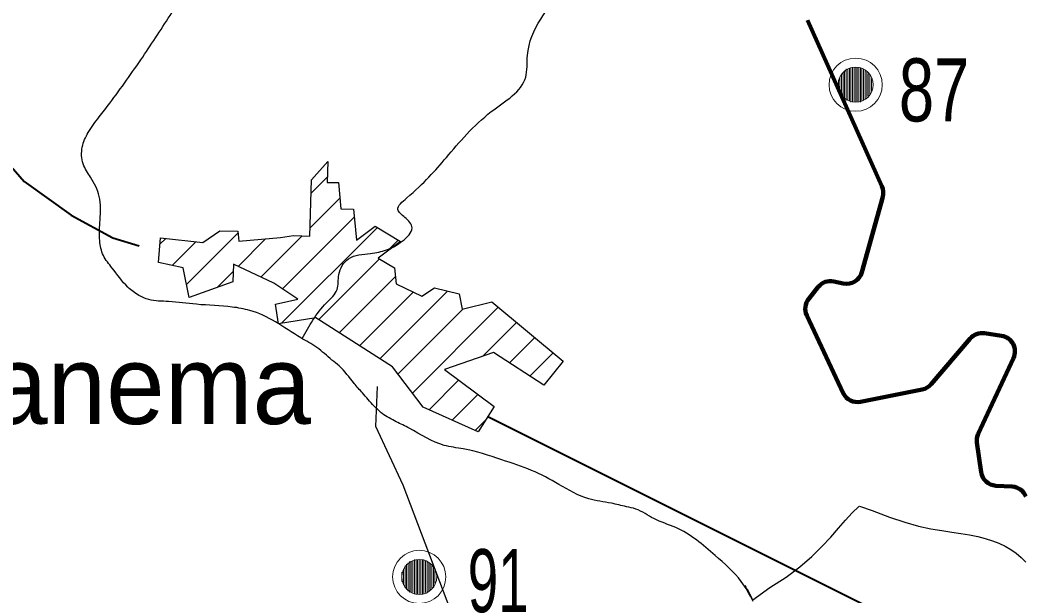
# Model space of a CAD drawing. Extents: x 553962 to 842807, y 8883888 to 9032388.
# Drawn here: x 690520 to 696901, y 8961682 to 8965336 of the extents above; entities that cross this region are included whole.
import ezdxf

# ---------------------------------------------------------------- set-up
doc = ezdxf.new("R2010")
doc.units = 0
doc.header["$LTSCALE"] = 160
for name, color, linetype, lineweight in [('15', 7, 'Continuous', 25), ('21', 7, 'Continuous', 25), ('27', 7, 'Continuous', 90), ('28', 7, 'Continuous', 13), ('32', 7, 'Continuous', 13), ('33', 7, 'Continuous', 13), ('7', 7, 'Continuous', 90)]:
    doc.layers.add(name, color=color, linetype=linetype, lineweight=lineweight)
doc.layers.add('29', color=7, linetype='Continuous')

msp = doc.modelspace()

# ---------------------------------------------------------------- linework, layer by layer
at = {"layer": '15', "lineweight": 40}
for points in [[(678613, 8973314.2), (678848.5, 8973159.5), (686496, 8968269.5), (688991.1, 8966516.2), (690142.8, 8964774.6), (690545.4, 8964311.7), (690844.1, 8964097.1), (691108, 8963953.4), (691274.5, 8963904.3)], [(693487.4, 8962819.8), (696836.9, 8961144.8), (697384.1, 8960961.8), (697603.7, 8960973.6), (697714.4, 8961082.3), (698321.2, 8961447.4), (698679, 8961567.8), (700187.3, 8961472.5), (701093.5, 8961547), (704410.2, 8961560.7)]]:
    msp.add_lwpolyline(points, dxfattribs=at)
at = {"layer": '15'}
msp.add_lwpolyline([(691240.8, 8956578.2), (692809.2, 8960246.9), (693257.6, 8961326.5), (693299.9, 8961463.3), (692951.1, 8962385.1), (692776, 8962756.9), (692786.9, 8963010.2)], dxfattribs=at)
at = {"layer": '21'}
for points in [[(695169, 8961656.4), (695276, 8961734.9), (695379, 8961800.8), (695467.1, 8961866.7), (695542.4, 8961931.7), (695606.8, 8961994.7), (695662.7, 8962054.9), (695711.8, 8962111.2), (695756.5, 8962162.8), (695798.7, 8962208.5), (695840.2, 8962247.9), (695844.8, 8962251.7), (695925.7, 8962224.4), (696035.2, 8962181.1), (696132.7, 8962148.6), (696219.6, 8962124.8), (696297.2, 8962107.9), (696367.1, 8962095.8), (696430.6, 8962086.5), (696489, 8962078.1), (696543.7, 8962068.8), (696595, 8962058.2), (696643, 8962046), (696688, 8962031.9), (696729.9, 8962015.6), (696769, 8961997.1), (696805.5, 8961975.9), (696839.5, 8961951.8), (696871.2, 8961924.8), (696901.1, 8961895.4)], [(695116.9, 8961748), (695124.2, 8961736.8), (695131.2, 8961725.1), (695138.1, 8961712.9), (695144.8, 8961700.5), (695151.1, 8961688), (695157.2, 8961675.6), (695162.9, 8961663.6), (695168.2, 8961652.1)]]:
    msp.add_lwpolyline(points, dxfattribs=at)
for points in [[(695170.7, 8961646.8), (695094.7, 8961773.3), (694929.1, 8961938.8), (694680.8, 8962114.8), (694540.3, 8962171.7), (694427.3, 8962232.6), (694366.5, 8962247.8), (694270.9, 8962269.5), (694127.6, 8962297.8), (693938.6, 8962389.1), (693764.8, 8962478.2), (693575.8, 8962545.5), (693330.4, 8962615.1), (693210.9, 8962636.8), (692989.3, 8962745.5), (692906.8, 8962786.8), (692817.7, 8962838.9), (692765.6, 8962886.7), (692691.7, 8962969.3), (692639.6, 8963030.2), (692544, 8963141), (692498.4, 8963178), (692402.8, 8963258.4), (692300.7, 8963319.2), (692140, 8963421.4), (691977.1, 8963493.1), (691866.3, 8963514.8), (691638.2, 8963532.2), (691462.3, 8963549.6), (691336.3, 8963562.6), (691273.3, 8963588.7), (691203.8, 8963640.9), (691103.8, 8963762.6), (691048.1, 8963842.5), (691024.9, 8963935.4), (691027.8, 8964068.8), (691022, 8964216.8), (690966.8, 8964338.7), (690920.4, 8964422.8), (690914.6, 8964530.2), (690952.3, 8964623), (691022, 8964721.7), (691088.7, 8964808.7), (691297.6, 8965101.8), (691483.3, 8965383.2), (691582, 8965539.9), (691761.8, 8965929.2), (692017.2, 8966518.5), (692139.1, 8966942.3), (692231.9, 8967543.3), (692246.4, 8967740.7), (692124.5, 8967943.9), (691973.7, 8968039.7), (691700.9, 8968077.4), (691448.5, 8968103.5)], [(692309.3, 8963314.4), (692463.9, 8963541.7), (692531, 8963625.6), (692542.2, 8963720.6), (692603.7, 8963821.3), (692743.5, 8963854.8), (692844.1, 8963877.2), (692944.8, 8963933.1), (693006.3, 8964017), (692961.6, 8964084.1), (692916.8, 8964134.4), (692972.7, 8964207.1), (693224.3, 8964464.2), (693509.5, 8964755), (693727.5, 8964973.1), (693738.7, 8965112.8), (693822.6, 8965342.1), (694079.8, 8965632.8), (694225.2, 8965783.8), (694415.2, 8966001.8), (694560.6, 8966180.7), (694706, 8966376.4), (694935.2, 8966560.9), (695192.4, 8966717.5), (695455.2, 8966997.1), (695650.9, 8967226.3), (695768.8, 8967390)]]:
    msp.add_spline(points, degree=3, dxfattribs=at)
at = {"layer": '27'}
msp.add_spline([(637260.6, 8972975.8), (641524.5, 8971056.2), (652526.1, 8965412.7), (653164.3, 8965062.8), (670790.5, 8953770.1), (686194, 8943929.9), (696283.3, 8937647.1)], degree=3, dxfattribs=at)
at = {"layer": '28'}
for p, q in [((692365.3, 8964234.6), (692468.9, 8964338.2)), ((692359.1, 8964016.2), (692548.9, 8964206.1)), ((692184.8, 8963629.8), (692639.5, 8964084.5)), ((692179, 8963411.8), (692787, 8964019.8)), ((691407.5, 8963913.1), (691445, 8963950.7)), ((691576.6, 8963658), (691901.9, 8963983.3)), ((691903.2, 8963772.5), (692077.9, 8963947.2)), ((692047.7, 8963704.8), (692309.3, 8963966.4)), ((691485.5, 8963779), (691635.2, 8963928.7)), ((692840.5, 8963861.2), (692918.6, 8963939.3)), ((692413.9, 8963434.7), (692799.7, 8963820.4)), ((691770, 8963639.3), (691871.9, 8963741.1)), ((692543.3, 8963351.9), (692900.7, 8963709.3)), ((692672.7, 8963269.2), (693013.7, 8963610.2)), ((692802.1, 8963186.4), (693231.9, 8963616.2)), ((692917.3, 8963089.5), (693331.6, 8963503.8)), ((693009, 8962969.1), (693553, 8963513.1)), ((693453.6, 8963201.5), (693669.1, 8963417.1)), ((693624.5, 8963160.3), (693785.2, 8963321.1)), ((693753.4, 8963077.1), (693901.4, 8963225.1)), ((693114.7, 8962862.6), (693302.2, 8963050.1)), ((693261.1, 8962796.9), (693423.9, 8962959.7)), ((693407.5, 8962731.2), (693472.5, 8962796.2))]:
    msp.add_line(p, q, dxfattribs=at)
at = {"layer": '28', "lineweight": 25}
msp.add_lwpolyline([(692254, 8963968.8), (692357.6, 8963964.3), (692367.8, 8964321.4), (692472.5, 8964438.4), (692467.8, 8964306.3), (692539.2, 8964305.6), (692555.6, 8964137.6), (692634.2, 8964137), (692654, 8963940.3), (692772.6, 8964028.6), (692932.6, 8963930.8), (692792.3, 8963824.8), (692895.4, 8963763.2), (692905.3, 8963663.2), (693068.9, 8963583.2), (693148, 8963636.1), (693304.9, 8963599), (693325.5, 8963502.4), (693511.7, 8963547.2), (693965.8, 8963171.8), (693843, 8963019.3), (693523.2, 8963225.7), (693211.4, 8963117.6), (693527.4, 8962882.7), (693426, 8962722.9), (693077.2, 8962879.5), (692882.8, 8963134.7), (692396, 8963446.1), (692159.9, 8963408.8), (692139.5, 8963534), (692282.7, 8963564.9), (692129.9, 8963666.3), (691873.7, 8963786.3), (691869.2, 8963675.7), (691593.2, 8963574.5), (691555.5, 8963764.1), (691398.6, 8963797.6), (691410.7, 8963954.6), (691678.4, 8963923.7), (691786.2, 8963997.8), (691900.5, 8963996.8), (691907.1, 8963932.5), (692171.7, 8963955.2)], close=True, dxfattribs=at)
at = {"layer": '32'}
for p, q in [((693022, 8961912), (693022, 8961692)), ((693032, 8961912), (693032, 8961692)), ((693042, 8961912), (693042, 8961692)), ((693052, 8961912), (693052, 8961692)), ((693062, 8961912), (693062, 8961692)), ((693072, 8961912), (693072, 8961692)), ((693082, 8961912), (693082, 8961692)), ((692952, 8961852), (692952, 8961752)), ((692962, 8961872), (692962, 8961732)), ((692972, 8961882), (692972, 8961722)), ((692982, 8961892), (692982, 8961712)), ((692992, 8961902), (692992, 8961702)), ((693002, 8961902), (693002, 8961702)), ((693012, 8961902), (693012, 8961702)), ((693092, 8961902), (693092, 8961702)), ((693102, 8961902), (693102, 8961702)), ((693112, 8961892), (693112, 8961712)), ((693122, 8961882), (693122, 8961722)), ((693132, 8961872), (693132, 8961732)), ((693142, 8961862), (693142, 8961742)), ((693152, 8961842), (693152, 8961762)), ((692942, 8961832), (692942, 8961772))]:
    msp.add_line(p, q, dxfattribs=at)
for radius in [168.7, 111]:
    msp.add_circle((693052, 8961802), radius, dxfattribs=at)
at = {"layer": '33'}
for p, q in [((695791, 8965036), (695791, 8964816)), ((695801, 8965036), (695801, 8964816)), ((695811, 8965036), (695811, 8964816)), ((695821, 8965036), (695821, 8964816)), ((695831, 8965036), (695831, 8964816)), ((695841, 8965036), (695841, 8964816)), ((695851, 8965036), (695851, 8964816)), ((695721, 8964976), (695721, 8964876)), ((695731, 8964996), (695731, 8964856)), ((695741, 8965006), (695741, 8964846)), ((695751, 8965016), (695751, 8964836)), ((695761, 8965026), (695761, 8964826)), ((695771, 8965026), (695771, 8964826)), ((695781, 8965026), (695781, 8964826)), ((695861, 8965026), (695861, 8964826)), ((695871, 8965026), (695871, 8964826)), ((695881, 8965016), (695881, 8964836)), ((695891, 8965006), (695891, 8964846)), ((695901, 8964996), (695901, 8964856)), ((695911, 8964986), (695911, 8964866)), ((695711, 8964956), (695711, 8964896)), ((695921, 8964966), (695921, 8964886))]:
    msp.add_line(p, q, dxfattribs=at)
for radius in [168.7, 111]:
    msp.add_circle((695821, 8964926), radius, dxfattribs=at)
at = {"layer": '7'}
for p, q in [((695514.3, 8965336), (695987, 8964282.2)), ((695992.2, 8964214.7), (695860, 8963735.6)), ((695583.3, 8963642.2), (695523.1, 8963567.1)), ((695742.5, 8963664.5), (695682.5, 8963677.4)), ((695510.6, 8963462), (695742, 8962969.2)), ((696300.1, 8963025.2), (696546.5, 8963314.3)), ((696637.4, 8963348.4), (696746.4, 8963332.1)), ((696822.2, 8963190.9), (696598.4, 8962710.5)), ((695852.1, 8962913.6), (696243.6, 8962992)), ((696590.1, 8962654.1), (696616.8, 8962466.6)), ((696710.4, 8962380.9), (696813.4, 8962375.3))]:
    msp.add_line(p, q, dxfattribs=at)
for centre, start, end in [((695895.8, 8964241.2), 344.57453, 24.16266), ((695763.6, 8963762.2), 257.80556, 344.57453), ((695661.3, 8963579.7), 77.80556, 141.2848), ((695601.1, 8963504.5), 141.2848, 205.15261), ((696622.6, 8963249.5), 81.49733, 139.57037), ((696731.6, 8963233.2), 335.01972, 81.49733), ((696224, 8963090), 281.31534, 319.57037), ((695832.5, 8963011.7), 205.15261, 281.31534), ((696689.1, 8962668.3), 155.01971, 188.12616), ((696715.9, 8962480.8), 188.12617, 266.86211), ((696807.9, 8962275.4), 21.79084, 86.86211)]:
    msp.add_arc(centre, 100, start, end, dxfattribs=at)

# ---------------------------------------------------------------- texts
at = {"layer": '29'}
msp.add_text('Santana do Ipanema', height=500, dxfattribs=at).set_placement((686158.2, 8962772.4))
at = {"layer": '32', "width": 0.65}
msp.add_text('91', height=400, dxfattribs=at).set_placement((693359.8, 8961578.3))
at = {"layer": '33', "width": 0.75}
msp.add_text('87', height=400, dxfattribs=at).set_placement((696095.2, 8964693.1))

doc.saveas('drawing.dxf')
